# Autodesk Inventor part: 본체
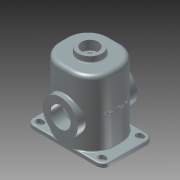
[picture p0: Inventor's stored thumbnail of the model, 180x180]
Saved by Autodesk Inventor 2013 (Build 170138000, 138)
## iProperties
Company: 한국ATC센터
Created: 2014-10
Part Number: 본체
Document SubType Name: Modeling
Designer: 한국ATC센터
Density: 2.71 g/cm^3
Material: 알루미늄 6061
Mass: 2951.39 g
Surface Area: 2149.45 cm^2
Volume: 1089.07 cm^3
Author: KYOUNG IL JANG
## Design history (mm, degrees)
sketch "스케치1"
  geometry: L1 (-70, 65)-(70, 65); L2 (70, 65)-(70, -65); L3 (70, -65)-(-70, -65); L4 (-70, -65)-(-70, 65); 3 further points
  constraints: 8 end point, 2 midpoint, 2 parallel, 1 horizontal, 1 horizontal alignment, 1 perpendicular, 1 vertical alignment
  dimensions: "d0" = 140 distance of L2.end L3.end; "d68" = 130 distance of L3.end L1.start
extrude "돌출1" new body sketch "스케치1" distance "d1" = 180; taper "d2" = 0 deg
fillet "모깎기1" dims "d3" = 55
feature "쉘1" dims "d4" = 10
sketch "스케치2"
  geometry: L1 (-70, 10)-(-70, -10) reference; L2 (-15, -65)-(-82, -65); L3 (-82, 65)-(-15, 65); L4 (-83, 57)-(-78, 57); L5 (-78, 41)-(-83, 41); L6 (-100, 47)-(-100, -47); A1 r 55 centre (-15, 10) between (-15, 65) and (-70, 10) reference; A2 r 55 centre (-15, -10) between (-70, -10) and (-15, -65) reference; A3 r 8 centre (-78, 49) between (-78, 41) and (-78, 57); A4 r 8 centre (-83, 49) between (-83, 57) and (-83, 41); A5 r 18 centre (-82, 47) between (-82, 65) and (-100, 47); A6 r 18 centre (-82, -47) between (-100, -47) and (-82, -65); 1 further point
  constraints: 10 end point, 9 tangent, 8 point on circle, 4 centre point, 2 parallel, 2 perpendicular, 1 equal radius
  dimensions: "d6" = 49 vertical distance of point (0, 0) A3.centre; "d8" = 16 distance between parallel lines of L4 L5; "d64" = 18 radius of A5; "d65" = 8 distance from line of A3.centre L1; "d66" = 30 distance between parallel lines of L6 L1; "d67" = 5 distance of A4.centre A3.centre
extrude "돌출2" join sketch "스케치2" distance "d9" = 10; taper "d10" = 0 deg
extrude "돌출3" cut sketch "스케치2" stored distance "d11" = 10; taper "d12" = 0 deg
sketch "스케치3"
  geometry: L1 (-65, 10)-(-65, 180) reference; L2 (-55, 0)-(-55, 170) reference; L3 (-77, 75)-(-45, 75); L4 (10, 0)-(-10, 0) reference; L5 (-77, 75)-(-77, 120.5); L6 (-77, 120.5)-(-55, 120.5); L7 (-55, 120.5)-(-45, 110.5); L8 (-45, 110.5)-(-45, 75); 3 further points
  constraints: 10 end point, 4 perpendicular, 1 point on line
  dimensions: "d13" = 75 distance between parallel lines of L3 L4; "d14" = 12 distance from line of L1 L3.start; "d15" = 10 distance from line of L3.end L2; "d16" = 91 diameter of L6 L3; "d17" = 135 deg angle of L7 L2
revolve "회전1" sketch "스케치3" stored, may be unused: angle "d18" = 90 deg
sketch "스케치4"
  geometry: C1 r 45.5 at (0, 0) reference; 2 further points
  constraints: 1 vertical alignment
  dimensions: "d19" = 35 distance of C1.centre point (0, 35)
hole "구멍1" sketch "스케치4" at (0, 35) diameter "d20" = 3.459; stored, may be unused: countersink angle "d24" = 90 deg, drill point angle "d26" = 118 deg; dims "d21" = 13, "d22" = 4, "d23" = 2, "d25" = 16
fillet "모깎기2" dims "d30" = 3
hole "구멍2" diameter "d33" = 52; stored, may be unused: countersink angle "d37" = 90 deg, drill point angle "d39" = 118 deg; dims "d31" = 10, "d32" = 10, "d34" = 13, "d35" = 4, "d36" = 2, "d38" = 16
sketch "스케치5"
  geometry: C1 r 31 at (0, 0); 1 further point
  constraints: 1 centre point, 1 coincident
  dimensions: "d40" = 62 diameter of C1
extrude "돌출4" join sketch "스케치5" distance "d41" = 15; taper "d42" = 0 deg
hole "구멍3" diameter "d45" = 43; stored, may be unused: countersink angle "d49" = 90 deg, drill point angle "d51" = 118 deg; dims "d43" = 10, "d44" = 10, "d46" = 13, "d47" = 4, "d48" = 2, "d50" = 16
fillet "모깎기3" dims "d52" = 3
fillet "모깎기4" dims "d53" = 3
chamfer "모따기1" distance "d55" = 1; stored, may be unused: second distance "d56" = 2, angle "d57" = 45 deg
sketch "스케치6"
  geometry: 2 further points
  constraints: 1 vertical alignment, 1 other
  dimensions: "d71" = 90 distance of point (0, 0) point (0, 90)
feature "엠보싱2" sketch "스케치6" dims "d0" = 140, "d68" = 130, "d72" = 1, "d73" = 0
fillet "모깎기6" dims "d74" = 10
sketch "스케치7"
  geometry: C1 r 15 at (0, 0); C2 r 21.5 at (0, 0) reference; C3 r 25 at (0, 0); 1 further point
  constraints: 2 centre point, 2 coincident
  dimensions: "d61" = 30 diameter of C1; "d75" = 50 diameter of C3
extrude "돌출5" join sketch "스케치7" distance "d62" = 10; taper "d63" = 0 deg
feature "면 이동1" dims "d76" = 1
node "솔리드1"
mirror "대칭1"
mirror "대칭2"
pattern_circular "원형 패턴1" dims angle "d28" = 360 deg
mirror "대칭3"
